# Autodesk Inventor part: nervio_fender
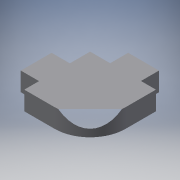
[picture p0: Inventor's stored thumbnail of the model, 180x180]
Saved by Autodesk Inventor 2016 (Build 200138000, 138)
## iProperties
Created: 2017-06
Part Number: nervio_fender
Material: Generic
Document SubType Name: Modeling
Designer: laboratorioesan
Density: 1 g/cm^3
Appearance: Default
Author: laboratorioesan
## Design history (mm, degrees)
sketch "Sketch1"
  geometry: L1 (0, 0)-(0, -30) reference; L2 (0, 0)-(-18.5, 0) reference; L3 (-18.5, -30)-(-18.5, 0) reference; L4 (0, -30)-(-18.5, -30) reference; L5 (50, 20)-(20, 20) reference; L6 (50, 20)-(50, 38.5) reference; L7 (20, 38.5)-(50, 38.5) reference; L8 (20, 20)-(20, 38.5) reference; L9 (0, 20.213)-(65, 20.213); L10 (65, 20.213)-(65, -44.787); L11 (65, -44.787)-(0, -44.787); L12 (0, -44.787)-(0, 20.213); L13 (20, 20)-(50, 20); L14 (50, 20)-(50, 38); L15 (50, 38)-(20, 38); L16 (20, 38)-(20, 20); L17 (0, 0)-(-18, 0); L18 (-18, 0)-(-18, -30); L19 (-18, -30)-(0, -30); L20 (0, -30)-(0, 0)
  constraints: 24 end point, 6 parallel, 3 horizontal, 3 perpendicular, 2 point on line
  dimensions: "d0" = 18 distance of L14.end L13.end; "d1" = 18 distance of L19.end L18.end; "d2" = 65 distance of L10.end L11.end; "d3" = 65 distance of L9.end L10.end
extrude "Extrusion1" new body sketch "Sketch1" distance "d4" = 18.5; taper "d5" = 0 deg
fillet "Fillet1" dims "d6" = 35
sketch "Sketch2"
  geometry: L1 (65, -9.787)-(65, 20.213) reference; L2 (65, 20.213)-(50, 20.213) reference; L3 (50, 20.213)-(50, 38) reference; L4 (50, 38)-(20, 38) reference; L5 (20, 38)-(20, 20.213) reference; L6 (20, 20.213)-(0, 20.213) reference; L7 (0, 20.213)-(0, 0) reference; L8 (0, 0)-(-18, 0) reference; L9 (-18, 0)-(-18, -30) reference; L10 (-18, -30)-(0, -30) reference; L11 (0, -30)-(0, -44.787) reference; L12 (0, -44.787)-(30, -44.787) reference; L13 (50, 38)-(20, 38) reference; L14 (65, 20.213)-(50, 20.213) reference; L15 (50, 38)-(50.2, 38); L16 (50.2, 38)-(50.2, 20.213); L17 (50.2, 20.213)-(50, 20.213); L18 (50, 20.213)-(50, 38); L19 (20, 20.213)-(0, 20.213) reference; L20 (20, 38)-(19.8, 38); L21 (19.8, 38)-(19.8, 20.213); L22 (19.8, 20.213)-(20, 20.213); L23 (20, 20.213)-(20, 38); L24 (0, 0)-(-18, 0) reference; L25 (0, 0)-(-18, 0); L26 (-18, 0)-(-18, 0.2); L27 (-18, 0.2)-(0, 0.2); L28 (0, 0.2)-(0, 0); L29 (0, -30)-(0, -44.787) reference; L30 (0, -30)-(-18, -30); L31 (-18, -30)-(-18, -30.2); L32 (-18, -30.2)-(0, -30.2); L33 (0, -30.2)-(0, -30); A1 r 35 centre (30, -9.787) between (30, -44.787) and (65, -9.787) reference
  constraints: 32 end point, 8 parallel, 4 horizontal, 4 perpendicular, 3 point on line
  dimensions: "d7" = 0.2 distance of L16.end L17.end; "d8" = 0.2 distance of L22.end L21.end; "d9" = 0.2 distance of L25.end L26.end; "d10" = 0.2 distance of L31.end L30.end
extrude "Extrusion2" join sketch "Sketch2" distance "d11" = 18.5; taper "d12" = 0 deg
body "Solid1"
node "Reference1"
node "Reference2"
node "Projected Loop1"
